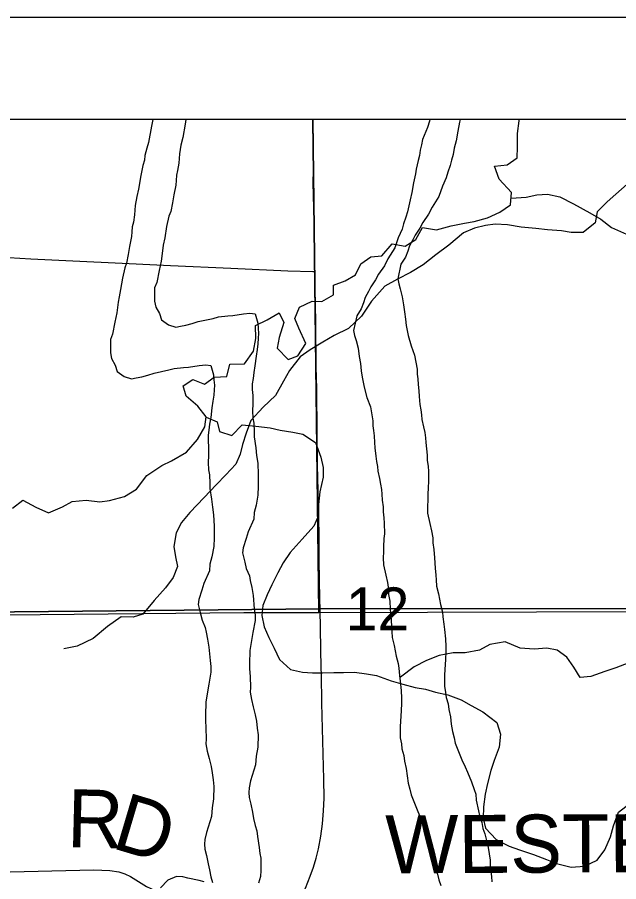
# Model space of a CAD drawing. Extents: x -21.1 to 50.3, y -4.9 to 22.1.
# Drawn here: x 3.578 to 4.167, y 20.154 to 21 of the extents above; entities that cross this region are included whole.
import ezdxf

# ---------------------------------------------------------------- set-up
doc = ezdxf.new("R2010")
doc.units = 0
for name, color, linetype in [('GM_X_Corporation', 7, 'Continuous'), ('GM_X_County', 7, 'Continuous'), ('GM_X_County_Road', 7, 'Continuous'), ('GM_X_County_Road_Text', 7, 'Continuous'), ('GM_X_Minor_River', 7, 'Continuous'), ('GM_X_Rail_Line_Text', 7, 'Continuous'), ('GM_X_Section_Text', 7, 'Continuous'), ('GM_X_Township_Road', 7, 'Continuous'), ('GM_X_Township_Road_Text', 7, 'Continuous'), ('SH_Cut_Line', 7, 'Continuous'), ('SH_Data', 7, 'Continuous')]:
    doc.layers.add(name, color=color, linetype=linetype)

msp = doc.modelspace()

# ---------------------------------------------------------------- linework, layer by layer
at = {"layer": 'GM_X_Corporation'}
for points in [[(3.86779, 20.9), (2.79839, 20.9), (2.80251, 20.40768), (3.80026, 20.41736), (3.87379, 20.41727)], [(4.88034, 20.9), (3.86779, 20.9), (3.87379, 20.41727), (4.83231, 20.42025), (4.88576, 20.41997)]]:
    msp.add_lwpolyline(points, close=True, dxfattribs=at)
at = {"layer": 'GM_X_County'}
msp.add_lwpolyline([(8.9, 14.74638), (8.9, 20.9), (2.1, 20.9), (2.1, 14.1), (8.89319, 14.1)], dxfattribs=at)
at = {"layer": 'GM_X_County_Road'}
msp.add_line((3.87493, 20.42048), (3.87473, 20.43048), dxfattribs=at)
for points in [[(3.86993, 20.75102), (3.86982, 20.76043), (3.86907, 20.80081), (3.86834, 20.83809), (3.86845, 20.85048), (3.86817, 20.87226), (3.86772, 20.9)], [(3.87473, 20.43048), (3.87398, 20.46851), (3.87394, 20.49025), (3.8736, 20.51201), (3.87254, 20.56166), (3.87206, 20.59269), (3.8717, 20.63619), (3.87116, 20.65793), (3.87068, 20.70141), (3.86993, 20.75102)], [(3.85589, 20.13792), (3.86052, 20.14762), (3.8653, 20.15915), (3.86842, 20.16798), (3.87111, 20.17695), (3.87329, 20.18605), (3.87562, 20.1983), (3.8773, 20.21066), (3.87838, 20.22308), (3.87882, 20.23554), (3.87866, 20.2542), (3.87777, 20.29146), (3.8768, 20.32874), (3.87623, 20.35666), (3.87608, 20.36289), (3.87493, 20.42048)]]:
    msp.add_lwpolyline(points, dxfattribs=at)
at = {"layer": 'GM_X_Minor_River'}
msp.add_line((3.74366, 20.9), (3.74282, 20.8955), dxfattribs=at)
for points in [[(3.57375, 20.51942), (3.58375, 20.52725), (3.59656, 20.52059), (3.60901, 20.51508), (3.62277, 20.52096), (3.63235, 20.52613), (3.64604, 20.52744), (3.65931, 20.52572), (3.66883, 20.5271), (3.68332, 20.53105), (3.69521, 20.53809), (3.70529, 20.55161), (3.71987, 20.56127), (3.72944, 20.56569), (3.744, 20.5742), (3.75483, 20.58658), (3.76224, 20.599), (3.76353, 20.60886), (3.75533, 20.61924), (3.74371, 20.62929), (3.74083, 20.63922), (3.75042, 20.64553), (3.76174, 20.6408), (3.77135, 20.64787), (3.78351, 20.64845), (3.78674, 20.66056), (3.80079, 20.66072), (3.80972, 20.67312), (3.81219, 20.68562), (3.81163, 20.69817), (3.82311, 20.70369), (3.83499, 20.71073), (3.8394, 20.70117), (3.835, 20.68642), (3.83294, 20.67619), (3.84378, 20.66501), (3.85333, 20.66866), (3.86112, 20.6807), (3.85413, 20.69562), (3.8501, 20.70519), (3.85483, 20.71613), (3.86707, 20.72202), (3.87656, 20.72188), (3.88806, 20.72816), (3.8882, 20.73766), (3.89967, 20.74204), (3.90963, 20.74797), (3.91474, 20.75853), (3.92472, 20.7656), (3.93537, 20.76658), (3.94542, 20.7782), (3.95831, 20.77611), (3.96866, 20.78241), (3.9753, 20.79409), (3.98894, 20.79198), (4.00343, 20.79594), (4.01638, 20.7984), (4.02591, 20.80016), (4.03888, 20.80376), (4.05112, 20.80927), (4.06148, 20.81633), (4.06243, 20.82847), (4.05048, 20.84158), (4.04574, 20.85419), (4.05829, 20.85551), (4.06789, 20.86258), (4.06843, 20.87283), (4.06826, 20.88613), (4.06997, 20.89865), (4.06975, 20.9)], [(3.71131, 20.9), (3.70992, 20.89329), (3.70696, 20.87731), (3.70547, 20.87199), (3.70323, 20.86475), (3.70287, 20.86019), (3.70138, 20.85487), (3.69953, 20.84498)], [(3.74282, 20.8955), (3.74061, 20.88219), (3.73875, 20.87496), (3.73728, 20.86621), (3.73657, 20.85709), (3.73547, 20.84987), (3.73435, 20.8453), (3.73399, 20.84036), (3.73364, 20.8358), (3.73179, 20.82629), (3.73031, 20.8183), (3.72884, 20.80994), (3.72696, 20.80537), (3.72473, 20.7951), (3.72289, 20.78407), (3.72141, 20.77684), (3.72068, 20.77152), (3.71921, 20.76126), (3.71736, 20.75213), (3.71514, 20.74034), (3.71289, 20.73501), (3.71296, 20.72209), (3.71413, 20.7164), (3.7176, 20.70996), (3.71953, 20.70389), (3.72641, 20.69899), (3.73366, 20.69675), (3.73822, 20.69754), (3.74354, 20.69871), (3.74963, 20.70026), (3.75571, 20.7022), (3.77015, 20.70531), (3.77547, 20.70687), (3.78461, 20.70767), (3.78955, 20.70808), (3.79982, 20.70966), (3.80629, 20.71046), (3.81124, 20.70972), (3.81395, 20.70062), (3.81436, 20.69568), (3.81477, 20.69037), (3.81442, 20.68581), (3.81407, 20.68049), (3.81334, 20.67478), (3.81223, 20.66832), (3.81114, 20.65882), (3.81004, 20.65235), (3.80931, 20.64627), (3.80858, 20.64133), (3.80861, 20.63563), (3.80902, 20.62993), (3.80907, 20.62157), (3.80873, 20.61473), (3.80915, 20.60752), (3.80994, 20.60258), (3.81036, 20.59461), (3.81039, 20.58929), (3.81197, 20.57866), (3.81278, 20.57107), (3.81396, 20.56348), (3.8144, 20.55246), (3.81447, 20.54106), (3.81414, 20.53232), (3.81229, 20.52244), (3.81043, 20.51521), (3.81008, 20.50875), (3.80444, 20.49618), (3.80258, 20.48971), (3.79958, 20.48058), (3.79885, 20.47563), (3.80118, 20.46653), (3.80274, 20.46046), (3.80583, 20.45326), (3.80661, 20.4487), (3.80817, 20.44188), (3.80936, 20.4339), (3.81057, 20.42099), (3.81137, 20.41492), (3.8114, 20.4096), (3.80918, 20.39781), (3.80623, 20.38032), (3.80593, 20.36702), (3.80596, 20.36208), (3.80638, 20.35487), (3.80682, 20.34385), (3.80647, 20.33929), (3.80765, 20.33208), (3.80959, 20.32487), (3.81154, 20.31729), (3.81272, 20.31084), (3.81351, 20.304), (3.81431, 20.29755), (3.814, 20.28539), (3.81253, 20.27664), (3.81181, 20.26828), (3.80695, 20.25268), (3.80547, 20.24583), (3.80511, 20.24127), (3.80552, 20.23634), (3.80708, 20.22988), (3.80865, 20.22192)], [(3.98252, 20.9), (3.98206, 20.89822), (3.98019, 20.89213), (3.97531, 20.88033), (3.9742, 20.875), (3.97308, 20.87006), (3.97235, 20.86473), (3.97086, 20.85979), (3.969, 20.85142), (3.96826, 20.84685), (3.96641, 20.83811), (3.96494, 20.8286), (3.96308, 20.82137), (3.96197, 20.81529), (3.96048, 20.80958), (3.95899, 20.80425), (3.95674, 20.79778), (3.95525, 20.79246), (3.95149, 20.78408), (3.94812, 20.77418), (3.94132, 20.7635), (3.93794, 20.75665), (3.93227, 20.74864), (3.92926, 20.74292), (3.92473, 20.73606), (3.92247, 20.73149), (3.91908, 20.72577), (3.91759, 20.72044), (3.91533, 20.71473), (3.9108, 20.70787), (3.90784, 20.69342), (3.90863, 20.68848), (3.91018, 20.68355), (3.91212, 20.67597), (3.91331, 20.66799), (3.91449, 20.66116), (3.91529, 20.65395), (3.91609, 20.64787), (3.91805, 20.63801), (3.92077, 20.62777), (3.92425, 20.61867), (3.92661, 20.605), (3.92663, 20.60007), (3.92742, 20.59551), (3.92783, 20.59019), (3.92825, 20.58374), (3.92866, 20.57842), (3.92946, 20.57045), (3.93025, 20.56513), (3.93105, 20.5602), (3.93145, 20.55564), (3.93301, 20.54843), (3.93419, 20.54312), (3.93498, 20.53781), (3.93538, 20.53325)], [(4.01198, 20.9), (4.01155, 20.89737), (4.0097, 20.88862), (4.00823, 20.87912), (4.00637, 20.87189), (4.00526, 20.8658), (4.00377, 20.8601), (4.00227, 20.85477), (4.00003, 20.8483), (3.99854, 20.84297), (3.99477, 20.83459), (3.9914, 20.8247), (3.98461, 20.81402), (3.98122, 20.80716), (3.97556, 20.79916), (3.97255, 20.79344), (3.96802, 20.78658), (3.96576, 20.782), (3.96237, 20.77629), (3.96087, 20.77096), (3.95862, 20.76525), (3.95409, 20.75839), (3.95113, 20.74393), (3.95192, 20.739), (3.95347, 20.73407), (3.95541, 20.72648), (3.9566, 20.71851), (3.95778, 20.71168), (3.95858, 20.70446), (3.95938, 20.69839), (3.96133, 20.68852), (3.96406, 20.67828), (3.96754, 20.66918), (3.9699, 20.65552), (3.96992, 20.65058), (3.97071, 20.64603), (3.97112, 20.64071), (3.97154, 20.63426), (3.97195, 20.62894), (3.97275, 20.62096), (3.97354, 20.61565), (3.97433, 20.61072), (3.97474, 20.60616), (3.9763, 20.59895), (3.97747, 20.59364), (3.97827, 20.58832), (3.97867, 20.58377)], [(3.69953, 20.84498), (3.69732, 20.83167), (3.69546, 20.82444), (3.69399, 20.8157), (3.69328, 20.80657), (3.69218, 20.79935), (3.69106, 20.79479), (3.6907, 20.78984), (3.69035, 20.78528), (3.6885, 20.77578), (3.68702, 20.76779), (3.68555, 20.75942), (3.68367, 20.75485), (3.68144, 20.74458), (3.6796, 20.73356), (3.67812, 20.72633), (3.67739, 20.72101), (3.67592, 20.71074), (3.67407, 20.70161), (3.67185, 20.68982), (3.6696, 20.68449), (3.66967, 20.67158), (3.67085, 20.66589), (3.67431, 20.65945), (3.67624, 20.65338), (3.68312, 20.64848), (3.69037, 20.64624), (3.69493, 20.64702), (3.70026, 20.64819), (3.70634, 20.64975), (3.71242, 20.65168), (3.72686, 20.6548), (3.73218, 20.65635), (3.74132, 20.65716), (3.74626, 20.65757), (3.75653, 20.65914), (3.763, 20.65994), (3.76795, 20.65921), (3.77067, 20.65011), (3.77107, 20.64517), (3.77148, 20.63985), (3.77113, 20.63529), (3.77078, 20.62997), (3.77005, 20.62427), (3.76894, 20.6178), (3.76785, 20.6083), (3.76675, 20.60184), (3.76602, 20.59575), (3.76529, 20.59081), (3.76532, 20.58511), (3.76573, 20.57942), (3.76578, 20.57106), (3.76544, 20.56422), (3.76586, 20.557), (3.76665, 20.55207), (3.76707, 20.54409), (3.7671, 20.53877), (3.76869, 20.52815), (3.76949, 20.52055), (3.77067, 20.51296), (3.77112, 20.50194), (3.77118, 20.49055), (3.77085, 20.48181), (3.769, 20.47192), (3.76714, 20.46469), (3.76679, 20.45823), (3.76115, 20.44566), (3.75929, 20.4392), (3.75629, 20.43006), (3.75556, 20.42512), (3.75789, 20.41601), (3.75945, 20.40994), (3.76254, 20.40274), (3.76332, 20.39819), (3.76488, 20.39136), (3.76607, 20.38339), (3.76728, 20.37048), (3.76808, 20.3644), (3.76811, 20.35908), (3.76589, 20.34729), (3.76295, 20.3298), (3.76264, 20.3165), (3.76267, 20.31157), (3.76309, 20.30435), (3.76353, 20.29334), (3.76318, 20.28878), (3.76436, 20.28157), (3.7663, 20.27436), (3.76825, 20.26677), (3.76943, 20.26032), (3.77023, 20.25348), (3.77102, 20.24703), (3.77071, 20.23487), (3.76924, 20.22613), (3.76852, 20.21776), (3.76366, 20.20216), (3.76218, 20.19532), (3.76182, 20.19075), (3.76223, 20.18582), (3.76379, 20.17937), (3.76536, 20.1714)], [(4.17875, 20.83911), (4.15599, 20.81938), (4.14613, 20.80952), (4.14423, 20.7989), (4.13247, 20.78942), (4.12072, 20.78942), (4.11124, 20.79094), (4.0976, 20.79207), (4.08622, 20.79321), (4.07182, 20.79472), (4.05855, 20.797), (4.04642, 20.79737), (4.03695, 20.79624), (4.02633, 20.79358), (4.01534, 20.78903), (4.00092, 20.77689), (3.98841, 20.76741), (3.97589, 20.75755), (3.96338, 20.75034), (3.95087, 20.74351), (3.93835, 20.73669), (3.92546, 20.72227), (3.91559, 20.70748), (3.9027, 20.69534), (3.88867, 20.68852), (3.87767, 20.68207), (3.86516, 20.67448), (3.8553, 20.66765), (3.84505, 20.65438), (3.83898, 20.64376), (3.8314, 20.62973), (3.81926, 20.61835), (3.80712, 20.60545), (3.80257, 20.59294), (3.79915, 20.58194), (3.79687, 20.57246), (3.79231, 20.5626), (3.78283, 20.55197), (3.77335, 20.54249)], [(4.06201, 20.82305), (4.0768, 20.82408), (4.08708, 20.8262), (4.09773, 20.8268), (4.10984, 20.82434), (4.12303, 20.8173), (4.13923, 20.8087), (4.14977, 20.80246), (4.16028, 20.79432), (4.17499, 20.78764)], [(3.7635, 20.6086), (3.77409, 20.60414), (3.7766, 20.59461), (3.7887, 20.59062), (3.79873, 20.60111), (3.81201, 20.59977), (3.82603, 20.59804), (3.83588, 20.59599), (3.84838, 20.5939), (3.85822, 20.59185), (3.87063, 20.58368), (3.87573, 20.56955), (3.87785, 20.55926), (3.87808, 20.54976), (3.87482, 20.53537), (3.8735, 20.52323), (3.87333, 20.51222), (3.86899, 20.50203), (3.8574, 20.48928), (3.8458, 20.47616), (3.83881, 20.46601), (3.83372, 20.45621), (3.82784, 20.44452), (3.82313, 20.43472), (3.81879, 20.42415), (3.81788, 20.41428), (3.82037, 20.40322), (3.82476, 20.3929), (3.82992, 20.38256), (3.83507, 20.37147), (3.84593, 20.36143), (3.85766, 20.35897), (3.86753, 20.35844), (3.87741, 20.35829), (3.88842, 20.3585), (3.89792, 20.35874), (3.90856, 20.35896), (3.92031, 20.35726), (3.93016, 20.35559), (3.94451, 20.35043), (3.95586, 20.34722), (3.96796, 20.344), (3.97819, 20.34233), (3.98802, 20.33952), (4.00013, 20.33667), (4.01298, 20.33192), (4.02277, 20.32645), (4.03445, 20.3202), (4.04796, 20.30973), (4.05158, 20.29828), (4.05024, 20.28539), (4.04548, 20.27254), (4.04229, 20.26271), (4.03906, 20.24984), (4.03662, 20.23962), (4.03491, 20.22711), (4.03474, 20.2161), (4.03686, 20.20619), (4.04732, 20.19501), (4.06014, 20.18874), (4.07034, 20.18516), (4.08394, 20.1804), (4.09678, 20.17565), (4.1066, 20.1717), (4.12098, 20.16806), (4.1339, 20.169), (4.14615, 20.1749), (4.1539, 20.18504), (4.15942, 20.19787), (4.16224, 20.20846), (4.16701, 20.22207), (4.17854, 20.23063)], [(3.97867, 20.58377), (3.97909, 20.57769), (3.97988, 20.57124), (3.97991, 20.5663), (3.98071, 20.5606), (3.98111, 20.55529), (3.98117, 20.54503), (3.98082, 20.54047), (3.98048, 20.53211), (3.98051, 20.52717), (3.98016, 20.52147), (3.9802, 20.51463), (3.98254, 20.50439), (3.98411, 20.49718), (3.98529, 20.49035), (3.98531, 20.48541), (3.98649, 20.47896), (3.98692, 20.47098), (3.98774, 20.46073), (3.98815, 20.45389), (3.98856, 20.44934), (3.98898, 20.44326), (3.99092, 20.43567), (3.99289, 20.42505), (3.99483, 20.41784), (3.99523, 20.41328), (3.99604, 20.40607), (3.99683, 20.40076), (3.99764, 20.39164), (3.99806, 20.38405), (3.99809, 20.37911), (3.99775, 20.37151), (3.99705, 20.36163), (3.9967, 20.35593), (3.99676, 20.34529), (3.99793, 20.33922), (3.99834, 20.33428), (4.00028, 20.32783), (4.00107, 20.32252), (4.00264, 20.31531), (4.00344, 20.3081), (4.00462, 20.30089), (4.00618, 20.29481), (4.00735, 20.2895), (4.01121, 20.27965), (4.01391, 20.27321), (4.017, 20.26638), (4.01931, 20.26108), (4.02317, 20.2516), (4.02587, 20.24402), (4.02742, 20.23947), (4.02784, 20.23377), (4.03018, 20.22315), (4.03097, 20.21859), (4.03329, 20.21177), (4.03446, 20.20608), (4.0364, 20.20077), (4.03834, 20.1928), (4.03952, 20.18749), (4.04069, 20.18104), (4.04149, 20.17496), (4.04152, 20.17003), (4.04231, 20.16395), (4.04272, 20.15902), (4.04313, 20.1537)], [(3.77335, 20.54249), (3.76159, 20.52997), (3.74756, 20.51518), (3.73921, 20.50532), (3.7339, 20.49546), (3.73162, 20.48181), (3.73351, 20.47195), (3.7354, 20.46247), (3.73122, 20.45147), (3.72364, 20.44161), (3.71264, 20.42909), (3.70126, 20.41581), (3.69178, 20.41278), (3.68003, 20.41316), (3.66675, 20.40367), (3.65272, 20.39191), (3.63718, 20.38433), (3.62391, 20.38167)], [(3.93538, 20.53325), (3.9358, 20.52718), (3.9366, 20.52072), (3.93662, 20.51578), (3.93742, 20.51009), (3.93783, 20.50477), (3.93788, 20.49451), (3.93753, 20.48996), (3.93719, 20.48159), (3.93722, 20.47666), (3.93688, 20.47096), (3.93691, 20.46412), (3.93925, 20.45387), (3.94082, 20.44666), (3.942, 20.43983), (3.94202, 20.43489), (3.9432, 20.42844), (3.94363, 20.42047), (3.94445, 20.41021), (3.94487, 20.40338), (3.94527, 20.39882), (3.94569, 20.39275), (3.94763, 20.38516), (3.9496, 20.37453), (3.95154, 20.36732), (3.95195, 20.36277), (3.95275, 20.35556), (3.95354, 20.35024), (3.95435, 20.34113), (3.95477, 20.33353), (3.9548, 20.32859), (3.95446, 20.32099), (3.95376, 20.31111), (3.95341, 20.30541), (3.95347, 20.29477), (3.95464, 20.2887), (3.95505, 20.28377), (3.95699, 20.27732), (3.95778, 20.272), (3.95935, 20.26479), (3.96015, 20.25758), (3.96133, 20.25037), (3.96289, 20.2443), (3.96406, 20.23899), (3.96792, 20.22913), (3.97062, 20.22269), (3.97371, 20.21587), (3.97602, 20.21056), (3.97988, 20.20108), (3.98259, 20.1935), (3.98413, 20.18895), (3.98455, 20.18326), (3.98689, 20.17263), (3.98768, 20.16808), (3.99, 20.16125), (3.99117, 20.15556), (3.99311, 20.15025)], [(4.17735, 20.36808), (4.16445, 20.36315), (4.15384, 20.35973), (4.14019, 20.3548), (4.12958, 20.35366), (4.12351, 20.3639), (4.1167, 20.37376), (4.10722, 20.38059), (4.09699, 20.38248), (4.08448, 20.38134), (4.07083, 20.38248), (4.05605, 20.38854), (4.04127, 20.38589), (4.03103, 20.38058), (4.017, 20.37792), (4.00525, 20.37792), (3.9916, 20.37526), (3.97909, 20.37033), (3.96696, 20.36426), (3.95368, 20.35402)], [(3.80865, 20.22192), (3.80982, 20.21584), (3.81138, 20.20901), (3.81293, 20.2037), (3.81373, 20.19801), (3.81531, 20.18738), (3.81611, 20.18131), (3.81689, 20.17675), (3.81696, 20.16498), (3.81661, 20.1589), (3.81475, 20.15243)], [(3.76536, 20.1714), (3.76653, 20.16533), (3.7681, 20.1585), (3.76965, 20.15319)], [(3.76145, 20.15365), (3.75649, 20.15514), (3.74544, 20.15736), (3.74048, 20.15847), (3.73439, 20.15882), (3.72604, 20.15535), (3.71885, 20.14771)]]:
    msp.add_lwpolyline(points, dxfattribs=at)
at = {"layer": 'GM_X_Rail_Line_Text'}
for points in [[(8.9, 20.9), (2.80139, 20.9)], [(3.30961, 20.41539), (3.87473, 20.42102), (4.62093, 20.42151), (5.88332, 20.42279), (6.48301, 20.42563)], [(6.48301, 20.42563), (5.88332, 20.42279), (4.62093, 20.42151), (3.87473, 20.42102), (3.30961, 20.41539)]]:
    msp.add_lwpolyline(points, dxfattribs=at)
at = {"layer": 'GM_X_Township_Road'}
for points in [[(3.31241, 20.77811), (3.32745, 20.77753), (3.34956, 20.7765), (3.38994, 20.77436), (3.46432, 20.77072), (3.49628, 20.76898), (3.54846, 20.76606), (3.59175, 20.7636), (3.62595, 20.76206), (3.68803, 20.75892), (3.72842, 20.75694), (3.78746, 20.75433), (3.84339, 20.7519), (3.86786, 20.75109), (3.86993, 20.75102)], [(3.31053, 20.15796), (3.31225, 20.1581), (3.36808, 20.15937), (3.46116, 20.16184), (3.55736, 20.16323), (3.65354, 20.1654), (3.66896, 20.16485), (3.678, 20.16344), (3.68378, 20.16161), (3.68927, 20.15905), (3.70508, 20.14918), (3.71363, 20.14516), (3.71965, 20.14333), (3.72896, 20.14181), (3.76933, 20.13983), (3.80968, 20.13887), (3.85, 20.13804), (3.85589, 20.13792)]]:
    msp.add_lwpolyline(points, dxfattribs=at)
at = {"layer": 'SH_Cut_Line'}
msp.add_lwpolyline([(8.9, 16.40522), (8.9, 20.9), (2.1, 20.9)], dxfattribs=at)
at = {"layer": 'SH_Data'}
msp.add_line((2, 21), (9, 21), dxfattribs=at)

# ---------------------------------------------------------------- texts
at = {"layer": 'GM_X_County_Road_Text'}
msp.add_text('WESTERN', height=0.056818, rotation=0.29166, dxfattribs=at).set_placement((3.93891, 20.16195))
at = {"layer": 'GM_X_Section_Text'}
msp.add_text('12', height=0.041856, rotation=0.00001, dxfattribs=at).set_placement((3.90012, 20.40004))
at = {"layer": 'GM_X_Township_Road_Text'}
for s, rotation, p in [('R', 358.56742, (3.62679, 20.18777)), ('D', 343.41939, (3.66953, 20.18722))]:
    msp.add_text(s, height=0.05682, rotation=rotation, dxfattribs=at).set_placement(p)

doc.saveas('drawing.dxf')
